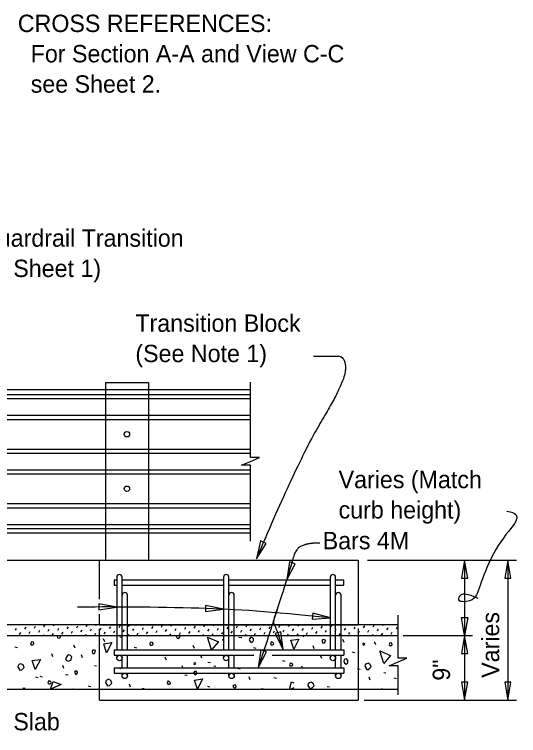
# Model space of a CAD drawing. Extents: x 21526.6 to 21595.9, y 56114.9 to 56157.2.
# Drawn here: x 21561.42 to 21567.28, y 56133.17 to 56141.55 of the extents above; entities that cross this region are included whole.
import ezdxf

# ---------------------------------------------------------------- set-up
doc = ezdxf.new("R2010")
doc.units = 0
for name, color, linetype in [('AdhocPoint_dp', 7, 'Continuous'), ('Border', 7, 'Continuous'), ('Patterning', 7, 'Continuous'), ('PlotBorder_dp', 7, 'Continuous'), ('SheetBorder_dp', 7, 'Continuous'), ('SheetLines_dp', 7, 'Continuous'), ('SubStrConc', 7, 'Continuous'), ('SubStrConc_h', 7, 'Continuous')]:
    doc.layers.add(name, color=color, linetype=linetype)

msp = doc.modelspace()

# ---------------------------------------------------------------- linework, layer by layer
at = {"layer": 'AdhocPoint_dp'}
for p, q in [((21554.3018, 56135.21), (21562.4118, 56135.21)), ((21565.8764, 56134.4601), (21554.3018, 56134.4601)), ((21554.3018, 56134.3351), (21565.8764, 56134.3351)), ((21565.8764, 56133.71), (21559.5217, 56133.71))]:
    msp.add_line(p, q, dxfattribs=at)
at = {"layer": 'Patterning'}
for p, q in [((21562.4788, 56137.2725), (21562.4788, 56135.21)), ((21562.4788, 56137.2725), (21562.9788, 56137.2725)), ((21562.9788, 56137.2725), (21562.9788, 56135.21)), ((21552.8484, 56137.1336), (21564.1633, 56137.1336)), ((21552.8484, 56137.0853), (21564.1633, 56137.0853)), ((21552.8484, 56136.8925), (21564.1633, 56136.8925)), ((21552.8484, 56136.8443), (21564.1633, 56136.8443)), ((21552.8484, 56136.5003), (21564.1633, 56136.5003)), ((21552.8484, 56136.4521), (21564.1633, 56136.4521)), ((21552.8484, 56136.2593), (21564.1633, 56136.2593)), ((21552.8484, 56136.2112), (21564.1633, 56136.2112)), ((21552.8484, 56135.8672), (21564.1633, 56135.8672)), ((21552.8484, 56135.819), (21564.1633, 56135.819)), ((21552.8484, 56135.6262), (21564.1633, 56135.6262)), ((21552.8484, 56135.5779), (21564.1633, 56135.5779)), ((21561.4954, 56134.4582), (21561.4965, 56134.4601)), ((21561.5442, 56134.4093), (21561.5572, 56134.4317)), ((21561.6548, 56134.4223), (21561.6678, 56134.4447)), ((21561.7655, 56134.4352), (21561.7784, 56134.4576)), ((21561.8761, 56134.4482), (21561.883, 56134.4601)), ((21561.9249, 56134.3994), (21561.9379, 56134.4218)), ((21562.0356, 56134.4123), (21562.0485, 56134.4347)), ((21562.1462, 56134.4253), (21562.1592, 56134.4477)), ((21562.2568, 56134.4383), (21562.2695, 56134.4601)), ((21562.3675, 56134.4512), (21562.3726, 56134.4601)), ((21562.4163, 56134.4024), (21562.4293, 56134.4248)), ((21562.5269, 56134.4154), (21562.5399, 56134.4377)), ((21562.6376, 56134.4283), (21562.6505, 56134.4507)), ((21562.7482, 56134.4413), (21562.7591, 56134.4601)), ((21562.8588, 56134.4542), (21562.8622, 56134.4601)), ((21562.9077, 56134.4054), (21562.9206, 56134.4278)), ((21563.0183, 56134.4184), (21563.0312, 56134.4408)), ((21563.1289, 56134.4313), (21563.1419, 56134.4537)), ((21563.2396, 56134.4443), (21563.2487, 56134.4601)), ((21563.3502, 56134.4573), (21563.3518, 56134.4601)), ((21563.399, 56134.4084), (21563.412, 56134.4308)), ((21563.5097, 56134.4214), (21563.5226, 56134.4438)), ((21563.6203, 56134.4344), (21563.6332, 56134.4568)), ((21563.7309, 56134.4473), (21563.7383, 56134.4601)), ((21563.7798, 56134.3985), (21563.7927, 56134.4209)), ((21563.8904, 56134.4115), (21563.9033, 56134.4338)), ((21564.001, 56134.4244), (21564.014, 56134.4468)), ((21564.1116, 56134.4374), (21564.1246, 56134.4598)), ((21564.2223, 56134.4503), (21564.2279, 56134.4601)), ((21564.2711, 56134.4015), (21564.2841, 56134.4239)), ((21564.3817, 56134.4145), (21564.3947, 56134.4369)), ((21564.4924, 56134.4274), (21564.5053, 56134.4498)), ((21564.603, 56134.4404), (21564.6144, 56134.4601)), ((21564.7151, 56134.4443), (21564.7243, 56134.4601)), ((21564.8258, 56134.4573), (21564.8274, 56134.4601)), ((21564.8746, 56134.4084), (21564.8876, 56134.4308)), ((21564.9852, 56134.4214), (21564.9982, 56134.4438)), ((21565.0959, 56134.4344), (21565.1088, 56134.4568)), ((21565.2065, 56134.4473), (21565.2139, 56134.4601)), ((21565.2553, 56134.3985), (21565.2683, 56134.4209)), ((21565.366, 56134.4115), (21565.3789, 56134.4338)), ((21565.4766, 56134.4244), (21565.4896, 56134.4468)), ((21565.5872, 56134.4374), (21565.6002, 56134.4598)), ((21565.6979, 56134.4503), (21565.7035, 56134.4601)), ((21565.7467, 56134.4015), (21565.7597, 56134.4239)), ((21565.8573, 56134.4145), (21565.8703, 56134.4369)), ((21561.4336, 56134.3964), (21561.4465, 56134.4187)), ((21561.4824, 56134.3475), (21561.4954, 56134.3699)), ((21561.593, 56134.3605), (21561.606, 56134.3829)), ((21561.7037, 56134.3734), (21561.7166, 56134.3958)), ((21561.7585, 56134.3351), (21561.7655, 56134.347)), ((21561.8143, 56134.3864), (21561.8273, 56134.4088)), ((21561.8631, 56134.3376), (21561.8761, 56134.36)), ((21561.9738, 56134.3505), (21561.9867, 56134.3729)), ((21562.0844, 56134.3635), (21562.0974, 56134.3859)), ((21562.145, 56134.3351), (21562.1462, 56134.3371)), ((21562.195, 56134.3765), (21562.208, 56134.3989)), ((21562.2482, 56134.3351), (21562.2568, 56134.35)), ((21562.3057, 56134.3894), (21562.3186, 56134.4118)), ((21562.3545, 56134.3406), (21562.3675, 56134.363)), ((21562.4651, 56134.3536), (21562.4781, 56134.376)), ((21562.5758, 56134.3665), (21562.5887, 56134.3889)), ((21562.6346, 56134.3351), (21562.6376, 56134.3401)), ((21562.6864, 56134.3795), (21562.6994, 56134.4019)), ((21562.7378, 56134.3351), (21562.7482, 56134.353)), ((21562.797, 56134.3925), (21562.81, 56134.4148)), ((21562.8459, 56134.3436), (21562.8588, 56134.366)), ((21562.9565, 56134.3566), (21562.9695, 56134.379)), ((21563.0671, 56134.3695), (21563.0801, 56134.3919)), ((21563.1243, 56134.3351), (21563.1289, 56134.3431)), ((21563.1778, 56134.3825), (21563.1907, 56134.4049)), ((21563.2274, 56134.3351), (21563.2396, 56134.3561)), ((21563.2884, 56134.3955), (21563.3013, 56134.4179)), ((21563.3372, 56134.3466), (21563.3502, 56134.369)), ((21563.4479, 56134.3596), (21563.4608, 56134.382)), ((21563.5585, 56134.3726), (21563.5714, 56134.395)), ((21563.6139, 56134.3351), (21563.6203, 56134.3461)), ((21563.6691, 56134.3855), (21563.6821, 56134.4079)), ((21563.718, 56134.3367), (21563.7309, 56134.3591)), ((21563.8286, 56134.3497), (21563.8415, 56134.372)), ((21563.9392, 56134.3626), (21563.9522, 56134.385)), ((21564.0004, 56134.3351), (21564.001, 56134.3362)), ((21564.0499, 56134.3756), (21564.0628, 56134.398)), ((21564.1035, 56134.3351), (21564.1116, 56134.3491)), ((21564.1605, 56134.3885), (21564.1734, 56134.4109)), ((21564.2093, 56134.3397), (21564.2223, 56134.3621)), ((21564.32, 56134.3527), (21564.3329, 56134.3751)), ((21564.4306, 56134.3656), (21564.4435, 56134.388)), ((21564.49, 56134.3351), (21564.4924, 56134.3392)), ((21564.5412, 56134.3786), (21564.5542, 56134.401)), ((21564.5931, 56134.3351), (21564.603, 56134.3522)), ((21564.6518, 56134.3916), (21564.6648, 56134.414)), ((21564.703, 56134.3351), (21564.7151, 56134.3561)), ((21564.764, 56134.3955), (21564.7769, 56134.4179)), ((21564.8128, 56134.3466), (21564.8258, 56134.369)), ((21564.9234, 56134.3596), (21564.9364, 56134.382)), ((21565.0341, 56134.3726), (21565.047, 56134.395)), ((21565.0895, 56134.3351), (21565.0959, 56134.3461)), ((21565.1447, 56134.3855), (21565.1577, 56134.4079)), ((21565.1935, 56134.3367), (21565.2065, 56134.3591)), ((21565.3042, 56134.3497), (21565.3171, 56134.372)), ((21565.4148, 56134.3626), (21565.4278, 56134.385)), ((21565.476, 56134.3351), (21565.4766, 56134.3362)), ((21565.5254, 56134.3756), (21565.5384, 56134.398)), ((21565.5791, 56134.3351), (21565.5872, 56134.3491)), ((21565.6361, 56134.3885), (21565.649, 56134.4109)), ((21565.6849, 56134.3397), (21565.6979, 56134.3621)), ((21565.7955, 56134.3527), (21565.8085, 56134.3751)), ((21562.4721, 56134.2625), (21562.458, 56134.2979)), ((21562.6448, 56134.3185), (21562.6766, 56134.315)), ((21563.8568, 56134.259), (21563.8427, 56134.2944)), ((21564.0294, 56134.315), (21564.0613, 56134.3114)), ((21565.2489, 56134.2557), (21565.2347, 56134.291)), ((21565.6176, 56134.2282), (21565.6035, 56134.2636)), ((21561.428, 56134.2036), (21561.4563, 56134.1965)), ((21562.1263, 56134.1877), (21562.1121, 56134.223)), ((21562.8127, 56134.2001), (21562.841, 56134.193)), ((21563.511, 56134.1841), (21563.4968, 56134.2195)), ((21564.1974, 56134.1965), (21564.2257, 56134.1894)), ((21564.903, 56134.1808), (21564.8889, 56134.2161)), ((21561.87, 56134.0869), (21561.8558, 56134.1223)), ((21562.214, 56134.0752), (21562.1999, 56134.1105)), ((21563.1862, 56134.0491), (21563.172, 56134.0845)), ((21563.5987, 56134.0716), (21563.5846, 56134.107)), ((21564.9908, 56134.0683), (21564.9767, 56134.1036)), ((21565.3441, 56134.1447), (21565.3724, 56134.1376)), ((21563.6672, 56134.0268), (21563.6973, 56134.0215)), ((21564.5329, 56134.0454), (21564.5612, 56134.0384)), ((21561.9955, 56133.9543), (21561.9831, 56133.9879)), ((21562.3519, 56133.9868), (21562.3767, 56133.9832)), ((21562.6277, 56133.9585), (21562.6578, 56133.9532)), ((21563.3802, 56133.9508), (21563.3678, 56133.9844)), ((21563.7366, 56133.9832), (21563.7614, 56133.9797)), ((21564.0124, 56133.955), (21564.0424, 56133.9497)), ((21564.7722, 56133.9474), (21564.7598, 56133.981)), ((21565.4045, 56133.9516), (21565.4345, 56133.9463)), ((21561.6655, 56133.8542), (21561.6938, 56133.8471)), ((21561.7179, 56133.8642), (21561.7462, 56133.8571)), ((21562.0143, 56133.8825), (21562.0443, 56133.8772)), ((21563.399, 56133.8789), (21563.429, 56133.8736)), ((21564.1609, 56133.8206), (21564.1485, 56133.8542)), ((21564.4349, 56133.8471), (21564.4632, 56133.8401)), ((21565.5529, 56133.8173), (21565.5406, 56133.8508)), ((21565.7105, 56133.9057), (21565.7353, 56133.9022)), ((21565.8269, 56133.8438), (21565.8552, 56133.8367)), ((21562.2777, 56133.7499), (21562.3042, 56133.7446)), ((21562.7705, 56133.7357), (21562.7581, 56133.7693)), ((21561.5188, 56133.7287), (21561.5453, 56133.7234)), ((21561.8135, 56133.71), (21561.8116, 56133.7152)), ((21562.9035, 56133.7251), (21562.93, 56133.7198)), ((21563.1969, 56133.71), (21563.1963, 56133.7116)), ((21563.6624, 56133.7464), (21563.6889, 56133.7411)), ((21564.2882, 56133.7216), (21564.3147, 56133.7163)), ((21565.0544, 56133.743), (21565.0809, 56133.7377)), ((21565.6802, 56133.7183), (21565.7067, 56133.713))]:
    msp.add_line(p, q, dxfattribs=at)
for points in [[(21561.6154, 56134.2283), (21561.6366, 56134.2283), (21561.6472, 56134.2389), (21561.6419, 56134.2584), (21561.6189, 56134.2602), (21561.6154, 56134.2495), (21561.6101, 56134.2407), (21561.6154, 56134.2283), (21561.6119, 56134.2319)], [(21561.915, 56134.3351), (21561.9142, 56134.3326), (21561.9177, 56134.3256)], [(21561.9177, 56134.3256), (21561.9265, 56134.3097), (21561.9477, 56134.3061), (21561.9566, 56134.322), (21561.9598, 56134.3351)], [(21562.4929, 56134.1357), (21562.4593, 56134.24), (21562.553, 56134.2524), (21562.4929, 56134.1357)], [(21563.0001, 56134.2248), (21563.0213, 56134.2248), (21563.0319, 56134.2354), (21563.0266, 56134.2549), (21563.0036, 56134.2566), (21563.0001, 56134.246), (21562.9948, 56134.2372), (21563.0001, 56134.2248), (21562.9965, 56134.2283)], [(21563.3008, 56134.3351), (21563.2988, 56134.3291), (21563.3024, 56134.322)], [(21563.3024, 56134.322), (21563.3112, 56134.3061), (21563.3324, 56134.3026), (21563.3413, 56134.3185), (21563.3448, 56134.3326), (21563.3424, 56134.3351)], [(21563.7121, 56134.1696), (21563.6644, 56134.3163), (21563.7899, 56134.2615), (21563.7121, 56134.1696)], [(21564.1486, 56134.2859), (21564.1592, 56134.2647), (21564.1769, 56134.2541), (21564.191, 56134.2647), (21564.1981, 56134.2753), (21564.1981, 56134.2965), (21564.1822, 56134.3124), (21564.1627, 56134.3106), (21564.1539, 56134.3018), (21564.1486, 56134.2859)], [(21564.4044, 56134.2281), (21564.4168, 56134.2263), (21564.4292, 56134.2316), (21564.4327, 56134.2423), (21564.4274, 56134.2511), (21564.4168, 56134.2582), (21564.4044, 56134.2635), (21564.3973, 56134.2493), (21564.3938, 56134.2387), (21564.4044, 56134.2281)], [(21564.6643, 56134.1779), (21564.6307, 56134.2822), (21564.7244, 56134.2945), (21564.6643, 56134.1779)], [(21564.7764, 56134.3351), (21564.7744, 56134.3291), (21564.7779, 56134.322)], [(21564.9933, 56134.2627), (21565.0022, 56134.2468), (21565.0216, 56134.2485), (21565.0304, 56134.2609), (21565.0322, 56134.2803), (21565.0198, 56134.2856), (21565.011, 56134.2874), (21565.0004, 56134.2839), (21564.9968, 56134.2803), (21564.9933, 56134.2627)], [(21565.4713, 56134.2251), (21565.4908, 56134.2339), (21565.4837, 56134.241), (21565.4713, 56134.2463), (21565.466, 56134.2339), (21565.4713, 56134.2251)], [(21565.7768, 56134.2179), (21565.798, 56134.2179), (21565.8086, 56134.2285), (21565.8033, 56134.248), (21565.7804, 56134.2497), (21565.7768, 56134.2391), (21565.7715, 56134.2303), (21565.7768, 56134.2179), (21565.7733, 56134.2215)], [(21562.0238, 56134.0498), (21562.0467, 56134.0374), (21562.0768, 56134.0498), (21562.0892, 56134.0869), (21562.0715, 56134.1046), (21562.0485, 56134.1099), (21562.0379, 56134.1028), (21562.0255, 56134.0834), (21562.0167, 56134.0675), (21562.0238, 56134.0498)], [(21562.3237, 56134.1423), (21562.3325, 56134.1264), (21562.3519, 56134.1282), (21562.3608, 56134.1406), (21562.3625, 56134.16), (21562.3502, 56134.1653), (21562.3413, 56134.1671), (21562.3307, 56134.1636), (21562.3272, 56134.16), (21562.3237, 56134.1423)], [(21565.7117, 56134.0122), (21565.664, 56134.1589), (21565.7895, 56134.1041), (21565.7117, 56134.0122)], [(21561.4605, 56133.9709), (21561.4834, 56133.9337), (21561.5064, 56133.9355), (21561.5153, 56133.9444), (21561.5347, 56133.9638), (21561.5223, 56133.9938), (21561.4976, 56134.008), (21561.4799, 56134.0009), (21561.4658, 56133.9868), (21561.4605, 56133.9709)], [(21561.6631, 56133.9402), (21561.6295, 56134.0445), (21561.7232, 56134.0569), (21561.6631, 56133.9402)], [(21563.5103, 56133.998), (21563.5298, 56134.0068), (21563.5227, 56134.0139), (21563.5103, 56134.0192), (21563.505, 56134.0068), (21563.5103, 56133.998)], [(21564.6215, 56133.9816), (21564.6427, 56133.9816), (21564.6533, 56133.9922), (21564.648, 56134.0116), (21564.625, 56134.0134), (21564.6215, 56134.0028), (21564.6162, 56133.994), (21564.6215, 56133.9816), (21564.618, 56133.9851)], [(21565.2454, 56134.0365), (21565.256, 56134.0152), (21565.2736, 56134.0046), (21565.2878, 56134.0152), (21565.2948, 56134.0259), (21565.2948, 56134.0471), (21565.2789, 56134.063), (21565.2595, 56134.0612), (21565.2507, 56134.0524), (21565.2454, 56134.0365)], [(21565.4907, 56133.9776), (21565.5137, 56133.9404), (21565.5366, 56133.9422), (21565.5455, 56133.9511), (21565.5649, 56133.9705), (21565.5526, 56134.0005), (21565.5278, 56134.0147), (21565.5101, 56134.0076), (21565.496, 56133.9935), (21565.4907, 56133.9776)], [(21562.1257, 56133.8949), (21562.1363, 56133.8842), (21562.1469, 56133.8913), (21562.1539, 56133.9019), (21562.1504, 56133.9196), (21562.1416, 56133.9214), (21562.1292, 56133.9196), (21562.1186, 56133.909), (21562.1257, 56133.8949)], [(21563.5103, 56133.8913), (21563.5209, 56133.8807), (21563.5316, 56133.8878), (21563.5386, 56133.8984), (21563.5351, 56133.9161), (21563.5262, 56133.9178), (21563.5139, 56133.9161), (21563.5033, 56133.9055), (21563.5103, 56133.8913)], [(21561.8205, 56133.7758), (21561.8328, 56133.774), (21561.8452, 56133.7793), (21561.8487, 56133.7899), (21561.8434, 56133.7988), (21561.8328, 56133.8058), (21561.8205, 56133.8111), (21561.8134, 56133.797), (21561.8099, 56133.7864), (21561.8205, 56133.7758)], [(21561.8428, 56133.711), (21561.8711, 56133.8029), (21561.9648, 56133.7658), (21561.8428, 56133.711)], [(21562.4785, 56133.7897), (21562.5015, 56133.7526), (21562.5245, 56133.7544), (21562.5333, 56133.7632), (21562.5528, 56133.7827), (21562.5404, 56133.8127), (21562.5156, 56133.8269), (21562.498, 56133.8198), (21562.4838, 56133.8056), (21562.4785, 56133.7897)], [(21563.2051, 56133.7723), (21563.2175, 56133.7705), (21563.2299, 56133.7758), (21563.2334, 56133.7864), (21563.2281, 56133.7952), (21563.2175, 56133.8023), (21563.2051, 56133.8076), (21563.1981, 56133.7935), (21563.1945, 56133.7829), (21563.2051, 56133.7723)], [(21563.547, 56133.7141), (21563.5134, 56133.8184), (21563.6071, 56133.8308), (21563.547, 56133.7141)], [(21563.9669, 56133.7339), (21563.9775, 56133.7233), (21563.9881, 56133.7304), (21563.9951, 56133.741), (21563.9916, 56133.7586), (21563.9828, 56133.7604), (21563.9704, 56133.7586), (21563.9598, 56133.748), (21563.9669, 56133.7339)], [(21564.6141, 56133.71), (21564.6405, 56133.7959), (21564.6652, 56133.7861)], [(21564.8288, 56133.7569), (21564.8518, 56133.7198), (21564.8748, 56133.7216), (21564.8836, 56133.7304), (21564.9031, 56133.7499), (21564.8907, 56133.7799), (21564.8659, 56133.794), (21564.8483, 56133.787), (21564.8341, 56133.7728), (21564.8288, 56133.7569)], [(21562.1099, 56133.71), (21562.1009, 56133.7145), (21562.0934, 56133.71)], [(21563.4875, 56133.71), (21563.4856, 56133.711), (21563.484, 56133.71)], [(21564.6652, 56133.7277), (21564.6258, 56133.71)], [(21564.8796, 56133.7067), (21564.8777, 56133.7077), (21564.876, 56133.7067)]]:
    msp.add_lwpolyline(points, dxfattribs=at)
at = {"layer": 'PlotBorder_dp'}
for p, q in [((21565.5209, 56135.21), (21567.2532, 56135.21)), ((21566.6495, 56135.21), (21566.6495, 56133.585)), ((21567.1495, 56135.21), (21567.1495, 56133.585)), ((21565.9364, 56134.335), (21566.742, 56134.335)), ((21565.4809, 56133.585), (21567.2532, 56133.585))]:
    msp.add_line(p, q, dxfattribs=at)
for points in [[(21564.1633, 56135.429), (21564.1633, 56136.3122), (21564.0599, 56136.3122), (21564.1633, 56136.3572), (21564.2666, 56136.4022), (21564.1633, 56136.4022), (21564.1633, 56137.2752)], [(21565.8764, 56133.6472), (21565.8764, 56133.9832), (21565.7731, 56133.9832), (21565.8764, 56134.0282), (21565.9797, 56134.0732), (21565.8764, 56134.0732), (21565.8764, 56134.5731)]]:
    msp.add_lwpolyline(points, dxfattribs=at)
for points in [[(21564.2319, 56135.2273), (21564.3454, 56135.4054), (21564.2804, 56135.4329)], [(21564.5839, 56134.9808), (21564.6819, 56135.1679), (21564.6148, 56135.1898)], [(21566.6495, 56135.21), (21566.6142, 56135.0017), (21566.6848, 56135.0017)], [(21567.1495, 56135.21), (21567.1142, 56135.0017), (21567.1848, 56135.0017)], [(21562.6093, 56134.6644), (21562.4019, 56134.7045), (21562.4003, 56134.634)], [(21563.8483, 56134.6403), (21563.6418, 56134.6846), (21563.6388, 56134.6141)], [(21565.0916, 56134.5393), (21564.8879, 56134.5955), (21564.8808, 56134.5253)], [(21566.6495, 56134.335), (21566.6142, 56134.5432), (21566.6848, 56134.5432)], [(21564.5411, 56134.1696), (21564.5162, 56134.3794), (21564.4485, 56134.3595)], [(21566.6495, 56134.335), (21566.6142, 56134.1267), (21566.6848, 56134.1267)], [(21564.2526, 56133.9599), (21564.3506, 56134.147), (21564.2835, 56134.1689)], [(21566.6495, 56133.585), (21566.6848, 56133.7933), (21566.6142, 56133.7933)], [(21567.1495, 56133.585), (21567.1848, 56133.7933), (21567.1142, 56133.7933)]]:
    msp.add_lwpolyline(points, close=True, dxfattribs=at)
for points, degree in [([(21564.8953, 56137.5794), (21565.0935, 56137.5794), (21565.2658, 56137.5794), (21565.2658, 56137.2865), (21564.723, 56136.3904), (21564.2319, 56135.2273)], 2), ([(21567.1386, 56135.7797), (21567.2493, 56135.7644), (21567.3017, 56135.6923), (21567.0236, 56135.4087), (21566.8353, 56134.952), (21566.7782, 56134.7407), (21566.6298, 56134.7236), (21566.5671, 56134.735), (21566.6013, 56134.8264), (21566.6698, 56134.8264), (21566.8011, 56134.7693)], 3), ([(21564.9691, 56135.4078), (21564.8456, 56135.4112), (21564.6854, 56135.3477), (21564.6319, 56135.124), (21564.2525, 56133.9599)], 2), ([(21565.0915, 56134.5393), (21564.3611, 56134.6135), (21563.7115, 56134.6624), (21562.4693, 56134.6694), (21562.1529, 56134.6645)], 3), ([(21564.4705, 56134.6317), (21564.412, 56134.4912), (21564.4698, 56134.4123), (21564.5411, 56134.1696)], 2)]:
    msp.add_open_spline(points, degree=degree, dxfattribs=at)
at = {"layer": 'SheetBorder_dp'}
for p, q in [((21564.1633, 56137.1891), (21552.8484, 56137.1891)), ((21564.1633, 56135.5224), (21552.8484, 56135.5224))]:
    msp.add_line(p, q, dxfattribs=at)
for centre in [(21562.7288, 56136.6724), (21562.7288, 56136.0393)]:
    msp.add_circle(centre, 0.0312, dxfattribs=at)
at = {"layer": 'SheetLines_dp'}
for p, q in [((21562.6097, 56135.0121), (21562.6097, 56134.1683)), ((21562.6722, 56134.1683), (21562.6722, 56135.0121)), ((21563.8493, 56135.0121), (21563.8493, 56134.1683)), ((21563.9118, 56134.1683), (21563.9118, 56135.0121)), ((21565.0889, 56135.0121), (21565.0889, 56134.1683)), ((21565.1514, 56134.1683), (21565.1514, 56135.0121)), ((21562.5785, 56134.9808), (21562.6097, 56134.9808)), ((21562.5785, 56134.9808), (21562.5785, 56134.9183)), ((21562.6722, 56134.9808), (21563.8493, 56134.9808)), ((21563.9118, 56134.9808), (21565.0889, 56134.9808)), ((21565.1514, 56134.9808), (21565.2451, 56134.9808)), ((21565.2451, 56134.9183), (21565.2451, 56134.9808)), ((21562.5785, 56134.9183), (21562.6097, 56134.9183)), ((21562.6722, 56134.9183), (21563.8493, 56134.9183)), ((21563.9118, 56134.9183), (21565.0889, 56134.9183)), ((21565.1514, 56134.9183), (21565.2451, 56134.9183)), ((21562.7347, 56134.1683), (21562.7347, 56134.8038)), ((21563.9743, 56134.1683), (21563.9743, 56134.8038)), ((21565.2139, 56134.1683), (21565.2139, 56134.8038)), ((21562.5785, 56134.1683), (21562.5785, 56134.1058)), ((21562.5785, 56134.1683), (21565.2451, 56134.1683)), ((21565.2451, 56134.1683), (21565.2451, 56134.1058)), ((21562.5785, 56134.1058), (21564.1999, 56134.1058)), ((21562.6097, 56134.1058), (21562.6097, 56134.0745)), ((21562.6722, 56133.9599), (21562.6722, 56134.1058)), ((21562.7347, 56133.9599), (21562.7347, 56134.1058)), ((21563.8493, 56134.1058), (21563.8493, 56134.0745)), ((21563.9118, 56133.9599), (21563.9118, 56134.1058)), ((21563.9743, 56133.9599), (21563.9743, 56134.1058)), ((21564.4139, 56134.1058), (21565.2451, 56134.1058)), ((21565.0889, 56134.1058), (21565.0889, 56134.0745)), ((21565.1514, 56133.9599), (21565.1514, 56134.1058)), ((21565.2139, 56133.9599), (21565.2139, 56134.1058)), ((21562.5785, 56133.9599), (21562.5785, 56133.8975)), ((21562.5785, 56133.9599), (21565.2451, 56133.9599)), ((21565.2451, 56133.9599), (21565.2451, 56133.8975)), ((21562.5785, 56133.8975), (21565.2451, 56133.8975)), ((21562.6722, 56133.8662), (21562.6722, 56133.8975)), ((21562.7347, 56133.8662), (21562.7347, 56133.8975)), ((21563.9118, 56133.8662), (21563.9118, 56133.8975)), ((21563.9743, 56133.8662), (21563.9743, 56133.8975)), ((21565.1514, 56133.8662), (21565.1514, 56133.8975)), ((21565.2139, 56133.8662), (21565.2139, 56133.8975))]:
    msp.add_line(p, q, dxfattribs=at)
for centre in [(21562.6409, 56134.0745), (21563.8805, 56134.0745), (21565.1201, 56134.0745), (21562.7034, 56133.8662), (21563.943, 56133.8662), (21565.1826, 56133.8662)]:
    msp.add_circle(centre, 0.0312, dxfattribs=at)
for centre, radius, start, end in [((21562.6409, 56135.0121), 0.0312, 0, 180), ((21563.8805, 56135.0121), 0.0312, 0, 180), ((21565.1201, 56135.0121), 0.0312, 0, 180), ((21562.7034, 56134.8038), 0.0312, 0, 180), ((21563.943, 56134.8038), 0.0312, 0, 180), ((21565.1826, 56134.8038), 0.0312, 0, 180), ((21562.8709, 56133.1683), 1, 90, 90.00000277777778)]:
    msp.add_arc(centre, radius, start, end, dxfattribs=at)
at = {"layer": 'SubStrConc'}
for p, q in [((21562.4118, 56135.21), (21565.4118, 56135.21)), ((21562.4118, 56134.7572), (21562.4118, 56135.21)), ((21565.4118, 56135.21), (21565.4118, 56134.46)), ((21562.4118, 56134.46), (21562.4118, 56134.5835))]:
    msp.add_line(p, q, dxfattribs=at)
at = {"layer": 'SubStrConc_h'}
for p, q in [((21562.4118, 56134.46), (21565.4118, 56134.46)), ((21562.4118, 56133.585), (21562.4118, 56134.4115)), ((21565.4118, 56134.417), (21565.4118, 56133.585)), ((21562.4118, 56133.585), (21565.4118, 56133.585))]:
    msp.add_line(p, q, dxfattribs=at)

# ---------------------------------------------------------------- texts
at = {"layer": 'Border'}
for s, p in [('Bars 4M', (21565.0015, 56135.3365)), ('Existing Approach Slab', (21559.1619, 56133.2344))]:
    msp.add_text(s, height=0.2016, dxfattribs=at).set_placement(p)
for s, p in [('Varies', (21567.0502, 56133.8443)), ('9"', (21566.4798, 56133.8109))]:
    msp.add_text(s, height=0.2016, rotation=90, dxfattribs=at).set_placement(p)
at = {"layer": 'PlotBorder_dp'}
for s, p in [('CROSS REFERENCES:', (21561.4616, 56141.3418)), ('  For Section A-A and View C-C ', (21561.4616, 56140.9898)), ('  see Sheet 2.', (21561.4616, 56140.6378)), ('Roadway Guardrail Transition', (21559.8207, 56138.8494)), ('(See Note 1, Sheet 1)', (21559.8207, 56138.4974)), ('Transition Block', (21562.8264, 56137.8614)), ('(See Note 1)', (21562.8264, 56137.5094)), ('Varies (Match', (21565.1861, 56136.0458)), ('curb height)', (21565.1861, 56135.6938))]:
    msp.add_text(s, height=0.2016, dxfattribs=at).set_placement(p)

doc.saveas('drawing.dxf')
